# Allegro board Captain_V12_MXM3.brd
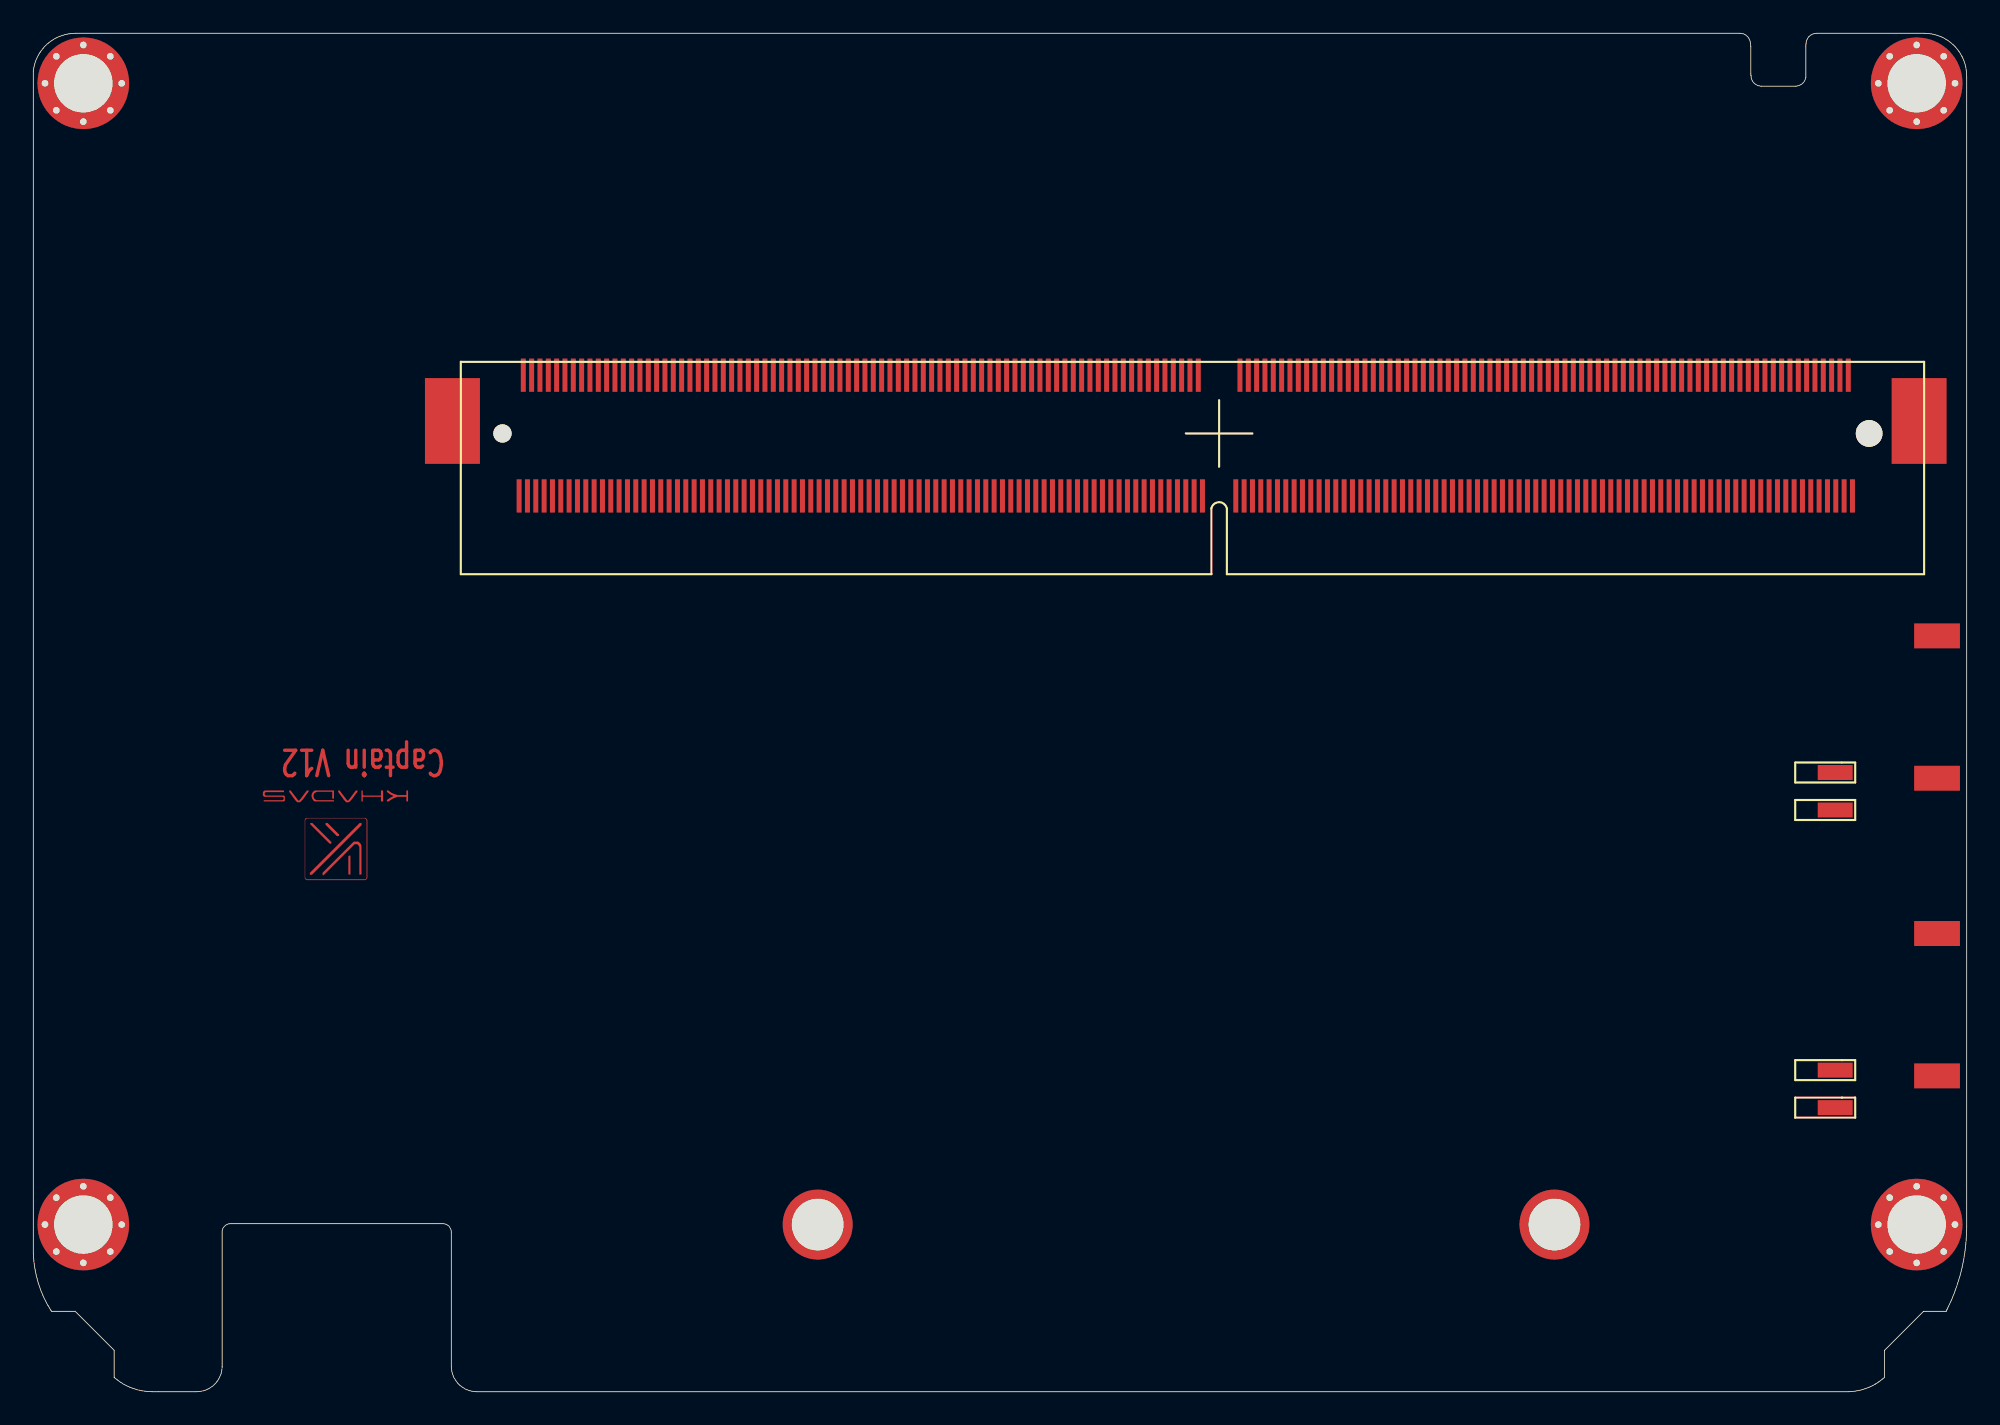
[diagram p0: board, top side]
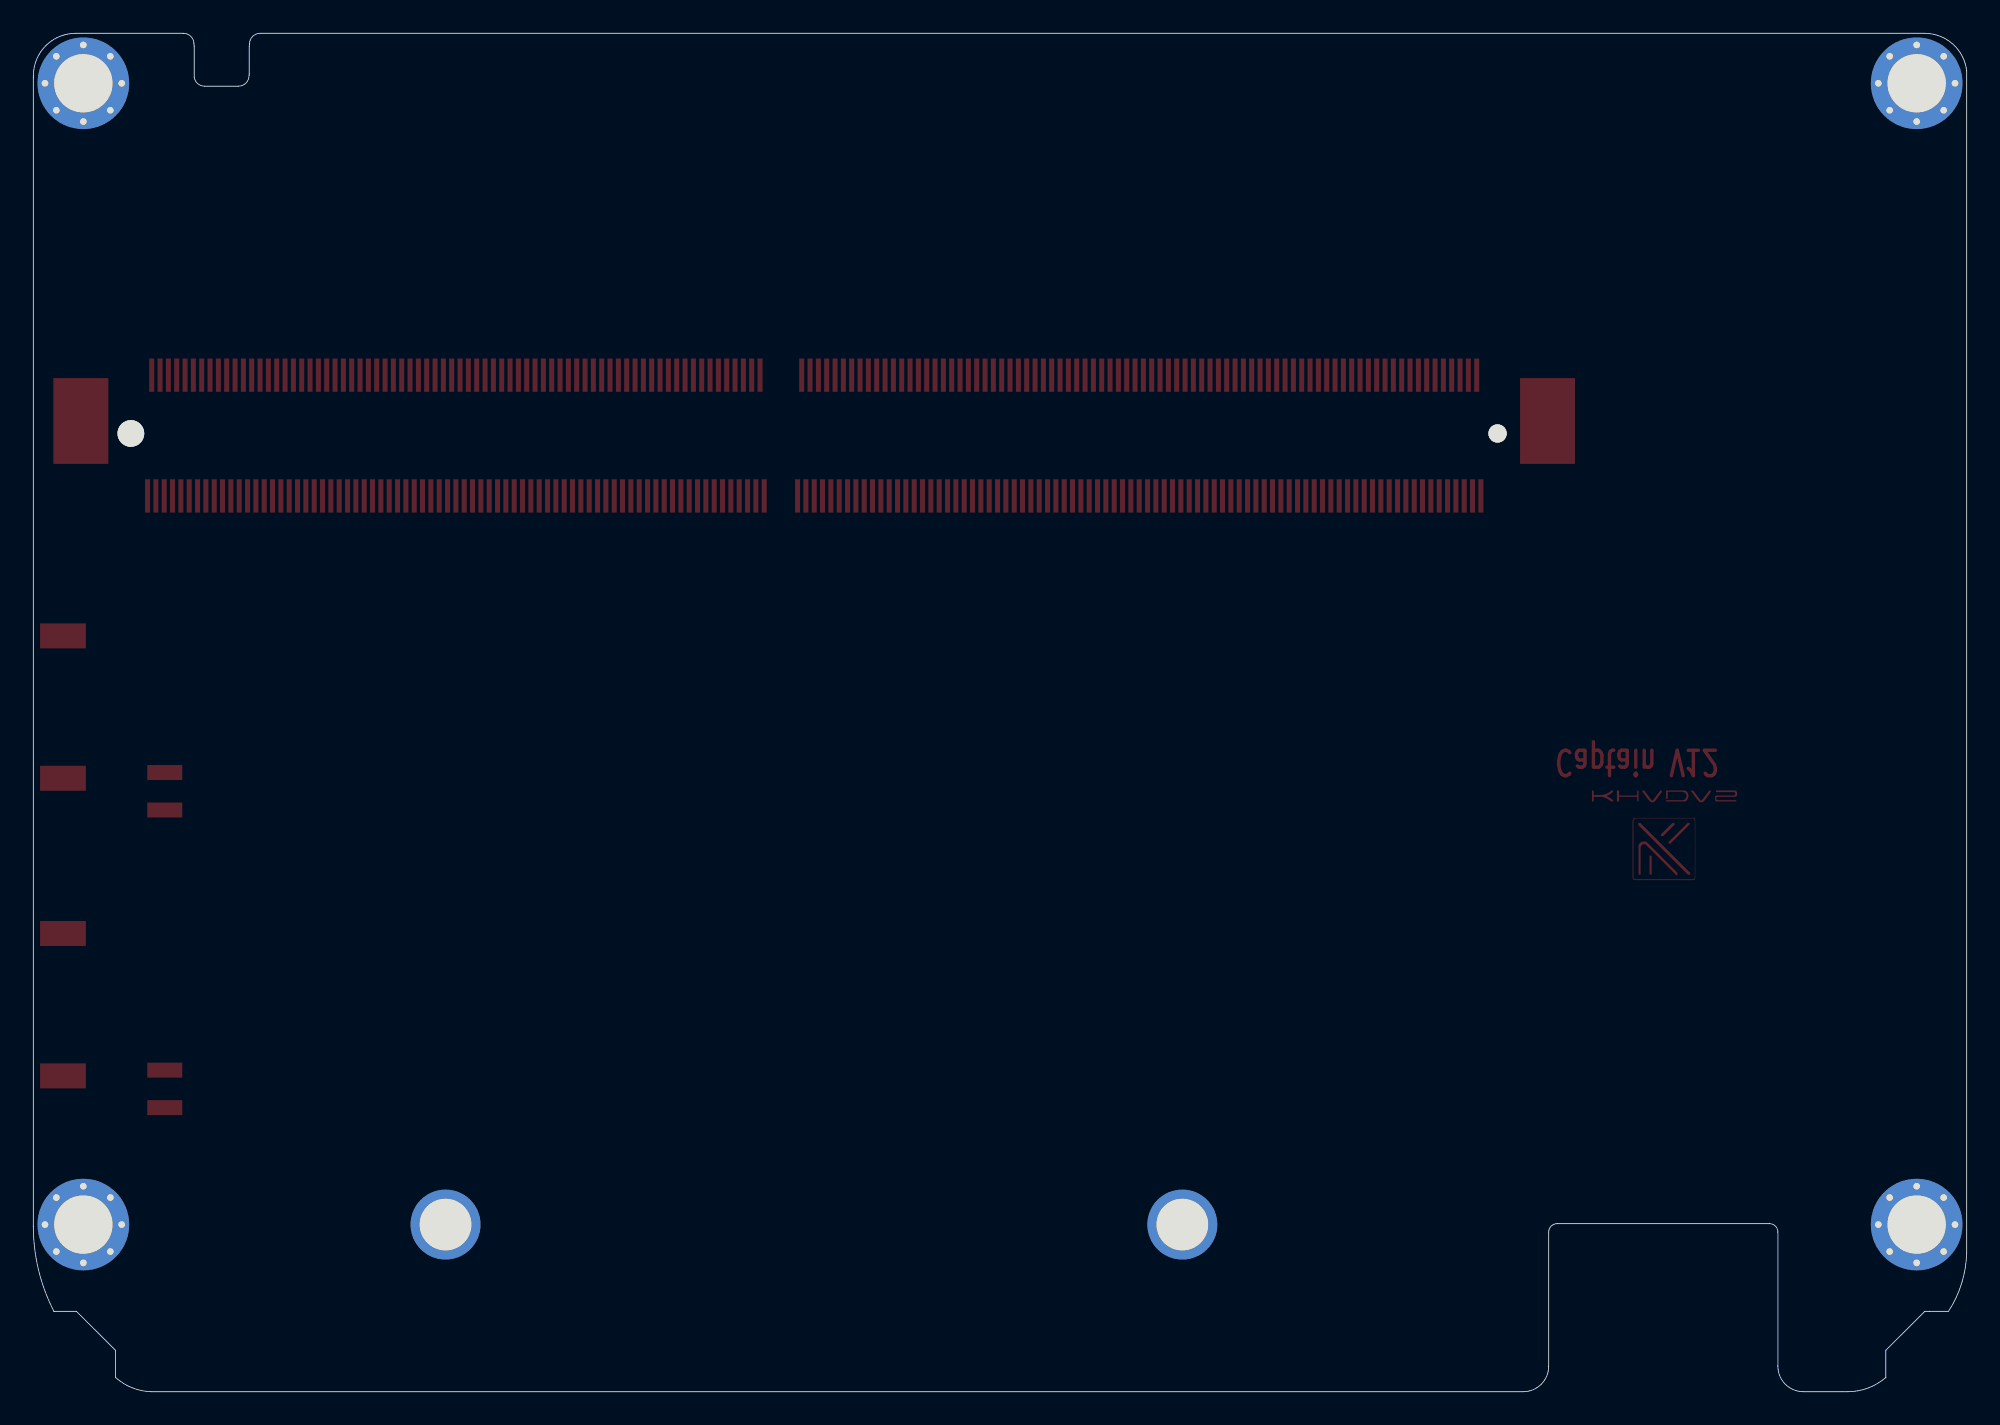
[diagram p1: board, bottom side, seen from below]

Outline 116 x 81.56 mm; copper layers: TOP, GND02, ART03, BOTTOM. Coordinates in mm from the lower left corner of the outline.
Outline path: 0,79.3 arc(0.83,80.91) 2.52,81.56 102.39,81.56 arc(102.84,81.37) 103.03,80.92 arc(103.03,80.85) 103.05,80.77 103.05,79.14 arc(103.06,79.08) 103.06,79.02 arc(103.24,78.57) 103.69,78.38 105.72,78.38 arc(106.13,78.53) 106.35,78.91 106.35,80.79 arc(106.36,80.85) 106.36,80.92 arc(106.55,81.37) 107,81.56 113.46,81.56 arc(115.25,80.81) 116,79.02 arc(116,78.95) 116,78.89 116,9.92 arc(115.69,7.3) 114.76,4.82 114.76,4.82 113.41,4.82 111.07,2.48 111.07,0.86 arc(110.08,0.24) 108.94,0 26.6,0 arc(25.53,0.45) 25.08,1.52 25.08,9.58 arc(24.93,9.94) 24.57,10.09 11.83,10.09 arc(11.48,9.94) 11.33,9.58 11.33,1.52 arc(10.88,0.45) 9.8,0 7.49,0 7.13,0 arc(5.93,0.22) 4.88,0.83 4.85,0.86 4.85,2.48 2.51,4.82 1.09,4.82 arc(0.31,6.49) 0,8.32 0,79.3

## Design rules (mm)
net group DA: nets DAN DAP
net group DB: nets DBN DBP
net group DC: nets DCN DCP
net group DD: nets DDN DDP
net group DIFFPAIR0: nets N69423239 N69423241
net group DIFFPAIR1: nets N69423297 N69423299
net group DIFFPAIR2: nets N69423181 N69423183
net group DIFFPAIR3: nets N69423123 N69423125
net group DP4: nets HOST1_DM HOST1_DP
net group EDP_AUXN: nets EDP_AUXN N69274556
net group EDP_AUXP: nets EDP_AUXP N69274538
net group EDP_TX0N: nets EDP_TX0N N69299365
net group EDP_TX0P: nets EDP_TX0P N69299363
net group EDP_TX1N: nets EDP_TX1N N69299351
net group EDP_TX1P: nets EDP_TX1P N69299349
net group EDP_TX2N: nets EDP_TX2N N69299335
net group EDP_TX2P: nets EDP_TX2P N69299337
net group EDP_TX3N: nets EDP_TX3N N69299322
net group EDP_TX3P: nets EDP_TX3P N69299325
net group PCIE_CLKN: nets N68532444 PCIE_CLKN
net group PCIE_CLKP: nets N68532441 PCIE_CLKP
net group PCIE_TX0N: nets N68528149 PCIE_TX0N
net group PCIE_TX0P: nets N68528147 PCIE_TX0P
net group PCIE_TX1N: nets N68528157 PCIE_TX1N
net group PCIE_TX1P: nets N68528155 PCIE_TX1P
net group PCIE_TX2N: nets N68528165 PCIE_TX2N
net group PCIE_TX2P: nets N68528163 PCIE_TX2P
net group PCIE_TX3N: nets N68528173 PCIE_TX3N
net group PCIE_TX3P: nets N68528171 PCIE_TX3P
net group MG_MIPI_RTX: nets MIPI_TX1/RX1_CLKN MIPI_TX1/RX1_CLKP MIPI_TX1/RX1_D0N MIPI_TX1/RX1_D0P MIPI_TX1/RX1_D1N MIPI_TX1/RX1_D1P MIPI_TX1/RX1_D2N MIPI_TX1/RX1_D2P MIPI_TX1/RX1_D3N MIPI_TX1/RX1_D3P
net group MG_MIPI_TX: nets MIPI_TX0_CLKN MIPI_TX0_CLKP MIPI_TX0_D0N MIPI_TX0_D0P MIPI_TX0_D1N MIPI_TX0_D1P MIPI_TX0_D2N MIPI_TX0_D2P MIPI_TX0_D3N MIPI_TX0_D3P
net group MG_MIPIRX: nets MIPI_RX0_CLKN MIPI_RX0_CLKP MIPI_RX0_D0N MIPI_RX0_D0P MIPI_RX0_D1N MIPI_RX0_D1P MIPI_RX0_D2N MIPI_RX0_D2P MIPI_RX0_D3N MIPI_RX0_D3P
net group MG_PCIE_RX: nets PCIE_RX0N PCIE_RX0P PCIE_RX1N PCIE_RX1P PCIE_RX2N PCIE_RX2P PCIE_RX3N PCIE_RX3P
net group PWR: nets CGND DCIN GND HPO_L HPO_R LOUT_L LOUT_R MIC2N MIC2P MICVDD VBAT VCC1V8_APIO2 VCC1V8_CODEC VCC1V8_S3 VCC3V0_SD VCC3V3_LAN VCC3V3_S0 VCC3V3_S5 VCC_1V2_IN VCC_1V8 VCC_3V0 VCC_CBAT VCC_TP VCCA1V8_AVDD VCCA1V8_S3 VDDA VSYS VSYS_3V3 VSYS_5V0

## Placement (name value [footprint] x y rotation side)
ANT1  ANT_SMT  [ANT_C]  114.22 23.23 90 top
ANT2  ANT_SMT  [ANT_C]  114.22 41.1 90 top
ANT3  ANT_P  [RF_340918]  108.11 17.06 0 top
ANT4  ANT_P  [RF_340918]  108.11 34.92 0 top
ANT5  ANT_P  [RF_340918]  108.11 19.31 0 top
ANT6  ANT_P  [RF_340918]  108.11 37.17 0 top
MT1  HOLE_8  [M3R5]  3 78.56 0 top
MT2  HOLE_8  [M3R5]  113 78.56 0 top
MT3  HOLE_8  [M3R5]  3 10.03 0 top
MT4  HOLE_8  [M3R5]  113 10.03 0 top
MT7  HOLE_8  [M2_3040]  47.06 10.03 0 top
MT8  HOLE_8  [M2_3040]  91.27 10.03 0 top
MXM314  -  [MXM314]  71.15 57.53 180 top
NOREF  -  []  18.21 33.17 180 top

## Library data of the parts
ANT1 ANT2 = ANT_0
ANT3-ANT6 = ANT_P_2
MT1-MT4 = HOLE_7
MT7 MT8 = HOLE_8
MXM314 = EF_6

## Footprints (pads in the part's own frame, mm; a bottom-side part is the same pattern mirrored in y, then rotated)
ANT_C
  rect 1.5x2.75 smd: 1(-4.274,0) 2(4.274,0)
M2_3040
  round 4.2 hole 3.1: 1(0,0)
M3R5
  round 0.5 hole 0.4: (-2.3,0) (-1.62,1.62) (-1.62,-1.62) (0,2.3) (0,-2.3) (1.62,1.62) (1.62,-1.62) (2.3,0)
  round 5.5 hole 3.5: 1(0,0)
MXM314
  rect 3.3x5.15 smd: (-42,-0.75) (46,-0.75)
  round 1.6 hole 1.6 unplated: (-39,0)
  round 1.092 hole 1.092 unplated: (43,0)
  rect 0.3x2 smd: P1(-37.75,-3.5) P2(-37.25,-3.5) P3(-36.75,-3.5) P4(-36.25,-3.5) P5(-35.75,-3.5) P6(-35.25,-3.5) P7(-34.75,-3.5) P8(-34.25,-3.5) P9(-33.75,-3.5) P10(-33.25,-3.5) P11(-32.75,-3.5) P12(-32.25,-3.5) P13(-31.75,-3.5) P14(-31.25,-3.5) P15(-30.75,-3.5) P16(-30.25,-3.5) P17(-29.75,-3.5) P18(-29.25,-3.5) P19(-28.75,-3.5) P20(-28.25,-3.5) P21(-27.75,-3.5) P22(-27.25,-3.5) P23(-26.75,-3.5) P24(-26.25,-3.5) P25(-25.75,-3.5) P26(-25.25,-3.5) P27(-24.75,-3.5) P28(-24.25,-3.5) P29(-23.75,-3.5) P30(-23.25,-3.5) P31(-22.75,-3.5) P32(-22.25,-3.5) P33(-21.75,-3.5) P34(-21.25,-3.5) P35(-20.75,-3.5) P36(-20.25,-3.5) P37(-19.75,-3.5) P38(-19.25,-3.5) P39(-18.75,-3.5) P40(-18.25,-3.5) P41(-17.75,-3.5) P42(-17.25,-3.5) P43(-16.75,-3.5) P44(-16.25,-3.5) P45(-15.75,-3.5) P46(-15.25,-3.5) P47(-14.75,-3.5) P48(-14.25,-3.5) P49(-13.75,-3.5) P50(-13.25,-3.5) P51(-12.75,-3.5) P52(-12.25,-3.5) P53(-11.75,-3.5) P54(-11.25,-3.5) P55(-10.75,-3.5) P56(-10.25,-3.5) P57(-9.75,-3.5) P58(-9.25,-3.5) P59(-8.75,-3.5) P60(-8.25,-3.5) P61(-7.75,-3.5) P62(-7.25,-3.5) P63(-6.75,-3.5) P64(-6.25,-3.5) P65(-5.75,-3.5) P66(-5.25,-3.5) P67(-4.75,-3.5) P68(-4.25,-3.5) P69(-3.75,-3.5) P70(-3.25,-3.5) P71(-2.75,-3.5) P72(-2.25,-3.5) P73(-1.75,-3.5) P74(-1.25,-3.5) P75(1.25,-3.5) P76(1.75,-3.5) P77(2.25,-3.5) P78(2.75,-3.5) P79(3.25,-3.5) P80(3.75,-3.5) P81(4.25,-3.5) P82(4.75,-3.5) P83(5.25,-3.5) P84(5.75,-3.5) P85(6.25,-3.5) P86(6.75,-3.5) P87(7.25,-3.5) P88(7.75,-3.5) P89(8.25,-3.5) P90(8.75,-3.5) P91(9.25,-3.5) P92(9.75,-3.5) P93(10.25,-3.5) P94(10.75,-3.5) P95(11.25,-3.5) P96(11.75,-3.5) P97(12.25,-3.5) P98(12.75,-3.5) P99(13.25,-3.5) P100(13.75,-3.5) P101(14.25,-3.5) P102(14.75,-3.5) P103(15.25,-3.5) P104(15.75,-3.5) P105(16.25,-3.5) P106(16.75,-3.5) P107(17.25,-3.5) P108(17.75,-3.5) P109(18.25,-3.5) P110(18.75,-3.5) P111(19.25,-3.5) P112(19.75,-3.5) P113(20.25,-3.5) P114(20.75,-3.5) P115(21.25,-3.5) P116(21.75,-3.5) P117(22.25,-3.5) P118(22.75,-3.5) P119(23.25,-3.5) P120(23.75,-3.5) P121(24.25,-3.5) P122(24.75,-3.5) P123(25.25,-3.5) P124(25.75,-3.5) P125(26.25,-3.5) P126(26.75,-3.5) P127(27.25,-3.5) P128(27.75,-3.5) P129(28.25,-3.5) P130(28.75,-3.5) P131(29.25,-3.5) P132(29.75,-3.5) P133(30.25,-3.5) P134(30.75,-3.5) P135(31.25,-3.5) P136(31.75,-3.5) P137(32.25,-3.5) P138(32.75,-3.5) P139(33.25,-3.5) P140(33.75,-3.5) P141(34.25,-3.5) P142(34.75,-3.5) P143(35.25,-3.5) P144(35.75,-3.5) P145(36.25,-3.5) P146(36.75,-3.5) P147(37.25,-3.5) P148(37.75,-3.5) P149(38.25,-3.5) P150(38.75,-3.5) P151(39.25,-3.5) P152(39.75,-3.5) P153(40.25,-3.5) P154(40.75,-3.5) P155(41.25,-3.5) P156(41.75,-3.5) S1(-38,3.75) S2(-37.5,3.75) S3(-37,3.75) S4(-36.5,3.75) S5(-36,3.75) S6(-35.5,3.75) S7(-35,3.75) S8(-34.5,3.75) S9(-34,3.75) S10(-33.5,3.75) S11(-33,3.75) S12(-32.5,3.75) S13(-32,3.75) S14(-31.5,3.75) S15(-31,3.75) S16(-30.5,3.75) S17(-30,3.75) S18(-29.5,3.75) S19(-29,3.75) S20(-28.5,3.75) S21(-28,3.75) S22(-27.5,3.75) S23(-27,3.75) S24(-26.5,3.75) S25(-26,3.75) S26(-25.5,3.75) S27(-25,3.75) S28(-24.5,3.75) S29(-24,3.75) S30(-23.5,3.75) S31(-23,3.75) S32(-22.5,3.75) S33(-22,3.75) S34(-21.5,3.75) S35(-21,3.75) S36(-20.5,3.75) S37(-20,3.75) S38(-19.5,3.75) S39(-19,3.75) S40(-18.5,3.75) S41(-18,3.75) S42(-17.5,3.75) S43(-17,3.75) S44(-16.5,3.75) S45(-16,3.75) S46(-15.5,3.75) S47(-15,3.75) S48(-14.5,3.75) S49(-14,3.75) S50(-13.5,3.75) S51(-13,3.75) S52(-12.5,3.75) S53(-12,3.75) S54(-11.5,3.75) S55(-11,3.75) S56(-10.5,3.75) S57(-10,3.75) S58(-9.5,3.75) S59(-9,3.75) S60(-8.5,3.75) S61(-8,3.75) S62(-7.5,3.75) S63(-7,3.75) S64(-6.5,3.75) S65(-6,3.75) S66(-5.5,3.75) S67(-5,3.75) S68(-4.5,3.75) S69(-4,3.75) S70(-3.5,3.75) S71(-3,3.75) S72(-2.5,3.75) S73(-2,3.75) S74(-1.5,3.75) S75(-1,3.75) S76(1,3.75) S77(1.5,3.75) S78(2,3.75) S79(2.5,3.75) S80(3,3.75) S81(3.5,3.75) S82(4,3.75) S83(4.5,3.75) S84(5,3.75) S85(5.5,3.75) S86(6,3.75) S87(6.5,3.75) S88(7,3.75) S89(7.5,3.75) S90(8,3.75) S91(8.5,3.75) S92(9,3.75) S93(9.5,3.75) S94(10,3.75) S95(10.5,3.75) S96(11,3.75) S97(11.5,3.75) S98(12,3.75) S99(12.5,3.75) S100(13,3.75) S101(13.5,3.75) S102(14,3.75) S103(14.5,3.75) S104(15,3.75) S105(15.5,3.75) S106(16,3.75) S107(16.5,3.75) S108(17,3.75) S109(17.5,3.75) S110(18,3.75) S111(18.5,3.75) S112(19,3.75) S113(19.5,3.75) S114(20,3.75) S115(20.5,3.75) S116(21,3.75) S117(21.5,3.75) S118(22,3.75) S119(22.5,3.75) S120(23,3.75) S121(23.5,3.75) S122(24,3.75) S123(24.5,3.75) S124(25,3.75) S125(25.5,3.75) S126(26,3.75) S127(26.5,3.75) S128(27,3.75) S129(27.5,3.75) S130(28,3.75) S131(28.5,3.75) S132(29,3.75) S133(29.5,3.75) S134(30,3.75) S135(30.5,3.75) S136(31,3.75) S137(31.5,3.75) S138(32,3.75) S139(32.5,3.75) S140(33,3.75) S141(33.5,3.75) S142(34,3.75) S143(34.5,3.75) S144(35,3.75) S145(35.5,3.75) S146(36,3.75) S147(36.5,3.75) S148(37,3.75) S149(37.5,3.75) S150(38,3.75) S151(38.5,3.75) S152(39,3.75) S153(39.5,3.75) S154(40,3.75) S155(40.5,3.75) S156(41,3.75) S157(41.5,3.75) S158(42,3.75)
RF_340918
  rect 2.1x0.9 smd: 1(0,0)

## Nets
GND: ANT5.1(PAD) ANT6.1(PAD) MT1.1 MT2.1 MT3.1 MT4.1 MT7.1 MT8.1 MXM314.P6 MXM314.P11 MXM314.P14 MXM314.P17 MXM314.P20 MXM314.P23 MXM314.P26 MXM314.P29 MXM314.P32 MXM314.P35 MXM314.P38 MXM314.P41 MXM314.P44 MXM314.P47 MXM314.P50 MXM314.P53 MXM314.P56 MXM314.P81 MXM314.P83 MXM314.P85 MXM314.P97 MXM314.P100 MXM314.P103 MXM314.P106 MXM314.P109 MXM314.P112 MXM314.P119 MXM314.P128 MXM314.P131 MXM314.P134 MXM314.P137 MXM314.P146 MXM314.P147 MXM314.P148 MXM314.S10 MXM314.S13 MXM314.S24 MXM314.S27 MXM314.S30 MXM314.S37 MXM314.S43 MXM314.S48 MXM314.S51 MXM314.S54 MXM314.S57 MXM314.S60 MXM314.S63 MXM314.S66 MXM314.S69 MXM314.S72 MXM314.S75 MXM314.S116 MXM314.S119 MXM314.S131 MXM314.S135 MXM314.S147 MXM314.S148 MXM314.S149 MXM314.S150
VBUS: MXM314.P150 MXM314.P151 MXM314.P152 MXM314.S151 MXM314.S152 MXM314.S153 MXM314.S154
VCC1V8_APIO2: MXM314.P125
VCC1V8_CODEC: MXM314.P123
VCC1V8_S3: MXM314.P145
VCC3V3_LAN: MXM314.P140 MXM314.P141 MXM314.P142
VCC3V3_S0: MXM314.P143
VCC3V3_S5: MXM314.S33
VCC_1V2_IN: MXM314.P122
VCC_1V8: MXM314.P124
VCC_3V0: MXM314.S124
VCC_CBAT: MXM314.P127
VCC_TP: MXM314.P144
VCCA1V8_S3: MXM314.S120
ADC_IN2: MXM314.P114
ADC_IN3: MXM314.P115
ADC_IN4: MXM314.P116
ADKEY_IN: MXM314.S121
APDS_INT: MXM314.S105
BAT_IO1: MXM314.P117
BAT_IO2: MXM314.P118
BT_PCM_CLK: MXM314.P10
BT_PCM_IN: MXM314.P8
BT_PCM_OUT: MXM314.P9
BT_PCM_SYNC: MXM314.P7
CAM0_PDN_H: MXM314.P96
CAM1_PDN_H: MXM314.P93
CARRIER_DET: MXM314.P113
CIF_CLKI: MXM314.P84
CIF_CLKO: MXM314.P82
CIF_D0: MXM314.P89
CIF_D1: MXM314.P92
CIF_D2: MXM314.P87
CIF_D3: MXM314.P94
CIF_D4: MXM314.P86
CIF_D6: MXM314.P90
CIF_D7: MXM314.P91
CIF_HREF: MXM314.P95
CIF_VSYNC: MXM314.P88
DBG_UART_RX: MXM314.S117
DBG_UART_TX: MXM314.S118
DCIN_ATTACH_H: MXM314.S42
EDP_AUXN: MXM314.P111
EDP_AUXP: MXM314.P110
EDP_TX0N: MXM314.P108
EDP_TX0P: MXM314.P107
EDP_TX1N: MXM314.P105
EDP_TX1P: MXM314.P104
EDP_TX2N: MXM314.P101
EDP_TX2P: MXM314.P102
EDP_TX3N: MXM314.P98
EDP_TX3P: MXM314.P99
GBE0_MDI0N: MXM314.P130
GBE0_MDI0P: MXM314.P129
GBE0_MDI1N: MXM314.P133
GBE0_MDI1P: MXM314.P132
GBE0_MDI2N: MXM314.P136
GBE0_MDI2P: MXM314.P135
GBE0_MDI3N: MXM314.P139
GBE0_MDI3P: MXM314.P138
GPIO0_A1: MXM314.S133
GPIO0_A2: MXM314.S107
GPIO0_B0: MXM314.S110
GPIO0_B1: MXM314.S111
GPIO0_B2: MXM314.S112
GPIO0_B3: MXM314.S113
GPIO0_B4: MXM314.S114
GPIO1_A0: MXM314.S132
GPIO1_A3: MXM314.S109
GPIO1_A4: MXM314.S108
GPIO1_B6: MXM314.S115
GPIO4_C4: MXM314.S15
GPIO4_D0: MXM314.S126
GPIO4_D4: MXM314.S44
GPIO4_D5: MXM314.S45
HAS_CHARGE_IC: MXM314.S41
HOST1_DM: MXM314.S12
HOST1_DP: MXM314.S11
I2C1_SCL: MXM314.S26
I2C1_SDA: MXM314.S25
I2C8_SCL_3V3: MXM314.S123
I2C8_SDA_3V3: MXM314.S122
I2S0_LRCK_RX: MXM314.S16
I2S0_LRCK_TX: MXM314.S17
I2S0_SCLK: MXM314.S14
I2S0_SDI0: MXM314.S18
I2S0_SDI1SDO3: MXM314.S19
I2S0_SDI2SDO2: MXM314.S20
I2S0_SDI3SDO1: MXM314.S21
I2S0_SDO0: MXM314.S22
I2S1_LRCK_RX: MXM314.P2
I2S1_LRCK_TX: MXM314.P1
I2S1_SCLK: MXM314.P5
I2S1_SDI0: MXM314.P4
I2S1_SDO0: MXM314.P3
I2S_CLK: MXM314.S23
MCU_ADC: MXM314.S32
MCU_FUNC: MXM314.P79
MCU_IR_IN: MXM314.S36
MCU_NRST: MXM314.S29
MCU_PA1: MXM314.S39
MCU_SWIM: MXM314.S28
MCU_TX: MXM314.S31
MICVDD: MXM314.P126
MIPI_RX0_CLKN: MXM314.P33
MIPI_RX0_CLKP: MXM314.P34
MIPI_RX0_D0N: MXM314.P39
MIPI_RX0_D0P: MXM314.P40
MIPI_RX0_D1N: MXM314.P36
MIPI_RX0_D1P: MXM314.P37
MIPI_RX0_D2N: MXM314.P30
MIPI_RX0_D2P: MXM314.P31
MIPI_RX0_D3N: MXM314.P27
MIPI_RX0_D3P: MXM314.P28
MIPI_TX0_CLKN: MXM314.P48
MIPI_TX0_CLKP: MXM314.P49
MIPI_TX0_D0N: MXM314.P54
MIPI_TX0_D0P: MXM314.P55
MIPI_TX0_D1N: MXM314.P51
MIPI_TX0_D1P: MXM314.P52
MIPI_TX0_D2N: MXM314.P45
MIPI_TX0_D2P: MXM314.P46
MIPI_TX0_D3N: MXM314.P42
MIPI_TX0_D3P: MXM314.P43
MIPI_TX1/RX1_CLKN: MXM314.P18
MIPI_TX1/RX1_CLKP: MXM314.P19
MIPI_TX1/RX1_D0N: MXM314.P12
MIPI_TX1/RX1_D0P: MXM314.P13
MIPI_TX1/RX1_D1N: MXM314.P15
MIPI_TX1/RX1_D1P: MXM314.P16
MIPI_TX1/RX1_D2N: MXM314.P21
MIPI_TX1/RX1_D2P: MXM314.P22
MIPI_TX1/RX1_D3N: MXM314.P24
MIPI_TX1/RX1_D3P: MXM314.P25
PCIE_CLKN: MXM314.S62
PCIE_CLKP: MXM314.S61
PCIE_TX0N: MXM314.S59
PCIE_TX0P: MXM314.S58
PCIE_TX1N: MXM314.S53
PCIE_TX1P: MXM314.S52
PCIE_TX2N: MXM314.S74
PCIE_TX2P: MXM314.S73
PCIE_TX3N: MXM314.S68
PCIE_TX3P: MXM314.S67
PMIC_EXT_EN: MXM314.S38
PWM1: MXM314.S125
RESET_IN_H: MXM314.S47
RTC_CLKO_SOC: MXM314.P80
SDMMC0_CLK: MXM314.S136
SDMMC0_CMD: MXM314.S134
SDMMC0_D0: MXM314.S138
SDMMC0_D1: MXM314.S139
SDMMC0_D2: MXM314.S140
SDMMC0_D3: MXM314.S141
SDMMC0_DET_L: MXM314.S137
SPDIF_TX: MXM314.S106
SPI3_CLK: MXM314.S130
SPI3_CS: MXM314.S129
SPI3_RXD: MXM314.S128
SPI3_TXD: MXM314.S127
USB_PWR_EN: MXM314.S6
USIC_DATA: MXM314.P121
USIC_STROBE: MXM314.P120
VSYS: MXM314.P154 MXM314.P155 MXM314.P156 MXM314.S155 MXM314.S156 MXM314.S157 MXM314.S158
VSYS_3V3: MXM314.S34 MXM314.S35 MXM314.S142 MXM314.S143 MXM314.S144 MXM314.S145
VSYS_5V0: MXM314.S7 MXM314.S8 MXM314.S9
WOL_EN: MXM314.S40
N69038338: ANT4.1(PAD)
N69038340: ANT1.1(ANT)
N69038342: ANT2.1(ANT)
N69038344: ANT3.1(PAD)
N69423123: MXM314.S49
N69423125: MXM314.S50
N69423181: MXM314.S55
N69423183: MXM314.S56
N69423239: MXM314.S64
N69423241: MXM314.S65
N69423297: MXM314.S70
N69423299: MXM314.S71

Pads without a net: ANT1 2; ANT2 2; MXM314 P57 P58 P59 P60 P61 P62 P63 P64 P65 P66 P67 P68 P69 P70 P71 P72 P73 P74 P75 P76 P77 P78 P149 P153 S1 S2 S3 S4 S5 S46 S76 S77 S78 S79 S80 S81 S82 S83 S84 S85 S86 S87 S88 S89 S90 S91 S92 S93 S94 S95 S96 S97 S98 S99 S100 S101 S102 S103 S104 S146

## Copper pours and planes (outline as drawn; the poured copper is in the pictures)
GND on TOP (solid shape): 16.75,34.14 17.88,33.01 17.88,32.94 17.87,32.91 17.83,32.9 17.78,32.91 16.62,34.06 16.61,34.12 16.62,34.13 16.64,34.14 16.74,34.14
GND on TOP (solid shape): 19.92,34.45 19.94,34.44 19.97,34.42 20,34.39 20.02,34.36 20.04,34.33 20.04,34.29 20.04,34.27 20.04,30.89 20.04,30.87 20.03,30.83 20.02,30.8 19.99,30.76 19.96,30.74 19.92,30.72 19.89,30.71 19.87,30.71 16.42,30.71 16.4,30.72 16.36,30.73 16.33,30.75 16.31,30.78 16.29,30.81 16.29,30.85 16.28,30.92 16.31,30.92 16.31,30.88 16.33,30.84 16.38,30.77 16.41,30.76 19.89,30.76 19.9,30.77 19.93,30.78 19.96,30.79 19.98,30.82 19.99,30.84 19.99,30.88 19.99,30.89 19.99,34.27 19.99,34.29 19.99,34.32 19.98,34.35 19.96,34.37 19.93,34.39 16.47,34.42 16.42,34.42 16.39,34.41 16.36,34.39 16.34,34.36 16.31,34.24 16.31,30.94 16.31,30.92 16.28,30.92 16.28,34.34 16.3,34.38 16.32,34.41 16.34,34.43 16.37,34.44 16.41,34.45

Small or netless copper shapes (teardrops, artwork), in the pictures only: 10 on TOP

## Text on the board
TOP: Captain V12
Ref Des/Assembly Top: R92 | R93
Board Geometry/Soldermask Top: Captain V12
DIMENSION: Via  Technic: | Spell Mode: | Bow and Twist Tolerance:<=0.75% | Inspectionstandard: | Compare With IPC File: | (unit:mil)MIN.track : 5                MIN.spacing : 5             MIN.hole:8 | Outline Profile: | Company Logo: | Silk Screen Colours: | Dielectric Material: | Soldermask Colours: | Surface Finished: | Finger Chamfer: | 3.If etch layer don't have  above impedance track pls ignore. | 1.STACKING (dielectric thickness can be adjusted beween +/-2mil,but don't less than 3.5 mil; | 2.Control Impedance (track width can be adjusted +/-0.5mil , but don't less than 4mil.) | if inspection is Gjb362A than don't less than 4 mil.) | Immersion Gold | Hasl Lead Free | Matte Black | Yes | White | Router | Required | All via (<=0.5mm) must be filled(except open soldermask via) | IPCII | FR4 | Pressfit holes: The tolerance of                 is+/-0.05mm | Angle | Board Thickness(MM): | Green | Specified Position | IPCIII | 20 | Bridge | Immersion Tin | No | Flash Gold | Yellow | Open Windows: | +/-5OHM | +/-10% | Immersion Silver | Blue | Hasl | Black | 30 | 1.6 | Gjb362B-2009 | V-cut | Only Date Code | None | Layers: | Gold Finger | Matte Green | Other | 45 | TOP | GND02 | ART03 | BOTTOM | By gerber | Not Appear | Stamp Hole | 4 | Osp | L1/L4 | L3 | 4.5 | 5.0/6.0 | 50 | 100 | L2/L3 | L2&L4 | REF LAYER | Think Different;Act Different; | Be Different;And Make a Difference. | Purchase   Order &  Specification   Sheet | Contact Ways: | URL: | Design By: | Lead Time: | Board Name: | REV: | Khadas | Captain V12 | 2019-05 | - | HTTPS://WWW.KHADAS.COM/ | C | 11 | 1 | 10 | 2 | 9 | 3 | 8 | 5 | 7 | 6 | H | D | G | F | B | E | A
0702: 1 | FAN | + | o | P | F | R | USB2.0 | M | B
User.6: FIGURE | SIZE | 8.0 | 15.748 | 47.244 | 86.614 | 122.047 | 137.795 | 35.433 | 43.0 | 43.307 | 51.18 | 62.99 | 63.0 | 70.866 | 43.307x15.748 | 47.244x31.496 | 78.74x39.37 | 86.614x27.559 | DRILL CHART: TOP to BOTTOM | ALL UNITS ARE IN MILS | PLATED | NON-PLATED | QTY | 1314 | 32 | 1 | 3 | 4 | 2
